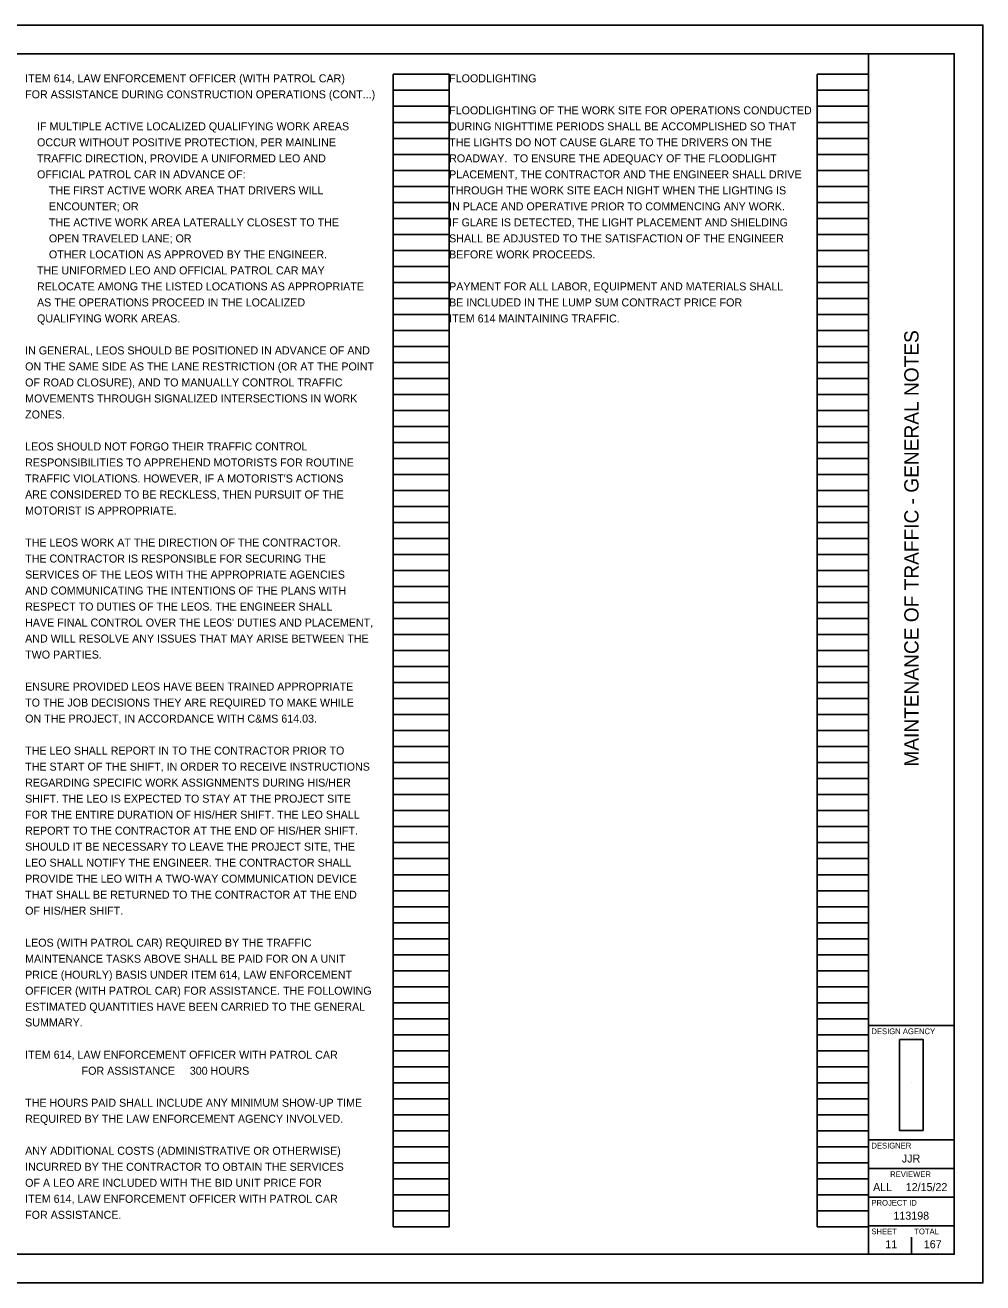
# Model space of a CAD drawing. Extents: x 0 to 34, y 0 to 22.
# Drawn here: x 17.24 to 34, y 0 to 22 of the extents above; entities that cross this region are included whole.
import ezdxf

# ---------------------------------------------------------------- set-up
doc = ezdxf.new("R2010")
doc.units = 0
for name, color, linetype in [('SH_Border', 7, 'Continuous'), ('SH_Cut_Line', 7, 'Continuous'), ('SH_Data', 7, 'Continuous'), ('SH_Text', 7, 'Continuous')]:
    doc.layers.add(name, color=color, linetype=linetype)

msp = doc.modelspace()

# ---------------------------------------------------------------- linework, layer by layer
at = {"layer": 'SH_Border'}
for p, q in [((32, 0.5), (32, 21.5)), ((32, 4.5), (33.5, 4.5)), ((32, 2.5), (33.5, 2.5)), ((32, 2), (33.5, 2)), ((32, 1.5), (33.5, 1.5)), ((32, 1), (33.5, 1))]:
    msp.add_line(p, q, dxfattribs=at)
msp.add_lwpolyline([(1.5, 21.5), (33.5, 21.5), (33.5, 0.5), (1.5, 0.5)], close=True, dxfattribs=at)
at = {"layer": 'SH_Cut_Line'}
msp.add_lwpolyline([(0, 0), (34, 0), (34, 22), (0, 22)], close=True, dxfattribs=at)
at = {"layer": 'SH_Data'}
for p, q in [((23.68, 0.98), (23.68, 21.14)), ((23.68, 21.14), (24.66, 21.14)), ((24.66, 0.98), (24.66, 21.14)), ((31.1, 0.98), (31.1, 21.14)), ((31.1, 21.14), (32, 21.14)), ((32, 0.98), (32, 21.14)), ((23.68, 20.86), (24.66, 20.86)), ((31.1, 20.86), (32, 20.86)), ((23.68, 20.58), (24.66, 20.58)), ((31.1, 20.58), (32, 20.58)), ((23.68, 20.3), (24.66, 20.3)), ((31.1, 20.3), (32, 20.3)), ((23.68, 20.02), (24.66, 20.02)), ((31.1, 20.02), (32, 20.02)), ((23.68, 19.74), (24.66, 19.74)), ((31.1, 19.74), (32, 19.74)), ((23.68, 19.46), (24.66, 19.46)), ((31.1, 19.46), (32, 19.46)), ((23.68, 19.18), (24.66, 19.18)), ((31.1, 19.18), (32, 19.18)), ((23.68, 18.9), (24.66, 18.9)), ((31.1, 18.9), (32, 18.9)), ((23.68, 18.62), (24.66, 18.62)), ((31.1, 18.62), (32, 18.62)), ((23.68, 18.34), (24.66, 18.34)), ((31.1, 18.34), (32, 18.34)), ((23.68, 18.06), (24.66, 18.06)), ((31.1, 18.06), (32, 18.06)), ((23.68, 17.78), (24.66, 17.78)), ((31.1, 17.78), (32, 17.78)), ((23.68, 17.5), (24.66, 17.5)), ((31.1, 17.5), (32, 17.5)), ((23.68, 17.22), (24.66, 17.22)), ((31.1, 17.22), (32, 17.22)), ((23.68, 16.94), (24.66, 16.94)), ((31.1, 16.94), (32, 16.94)), ((23.68, 16.66), (24.66, 16.66)), ((31.1, 16.66), (32, 16.66)), ((23.68, 16.38), (24.66, 16.38)), ((31.1, 16.38), (32, 16.38)), ((23.68, 16.1), (24.66, 16.1)), ((31.1, 16.1), (32, 16.1)), ((23.68, 15.82), (24.66, 15.82)), ((31.1, 15.82), (32, 15.82)), ((23.68, 15.54), (24.66, 15.54)), ((31.1, 15.54), (32, 15.54)), ((23.68, 15.26), (24.66, 15.26)), ((31.1, 15.26), (32, 15.26)), ((23.68, 14.98), (24.66, 14.98)), ((31.1, 14.98), (32, 14.98)), ((23.68, 14.7), (24.66, 14.7)), ((31.1, 14.7), (32, 14.7)), ((23.68, 14.42), (24.66, 14.42)), ((31.1, 14.42), (32, 14.42)), ((23.68, 14.14), (24.66, 14.14)), ((31.1, 14.14), (32, 14.14)), ((23.68, 13.86), (24.66, 13.86)), ((31.1, 13.86), (32, 13.86)), ((23.68, 13.58), (24.66, 13.58)), ((31.1, 13.58), (32, 13.58)), ((23.68, 13.3), (24.66, 13.3)), ((31.1, 13.3), (32, 13.3)), ((23.68, 13.02), (24.66, 13.02)), ((31.1, 13.02), (32, 13.02)), ((23.68, 12.74), (24.66, 12.74)), ((31.1, 12.74), (32, 12.74)), ((23.68, 12.46), (24.66, 12.46)), ((31.1, 12.46), (32, 12.46)), ((23.68, 12.18), (24.66, 12.18)), ((31.1, 12.18), (32, 12.18)), ((23.68, 11.9), (24.66, 11.9)), ((31.1, 11.9), (32, 11.9)), ((23.68, 11.62), (24.66, 11.62)), ((31.1, 11.62), (32, 11.62)), ((23.68, 11.34), (24.66, 11.34)), ((31.1, 11.34), (32, 11.34)), ((23.68, 11.06), (24.66, 11.06)), ((31.1, 11.06), (32, 11.06)), ((23.68, 10.78), (24.66, 10.78)), ((31.1, 10.78), (32, 10.78)), ((23.68, 10.5), (24.66, 10.5)), ((31.1, 10.5), (32, 10.5)), ((23.68, 10.22), (24.66, 10.22)), ((31.1, 10.22), (32, 10.22)), ((23.68, 9.94), (24.66, 9.94)), ((31.1, 9.94), (32, 9.94)), ((23.68, 9.66), (24.66, 9.66)), ((31.1, 9.66), (32, 9.66)), ((23.68, 9.38), (24.66, 9.38)), ((31.1, 9.38), (32, 9.38)), ((23.68, 9.1), (24.66, 9.1)), ((31.1, 9.1), (32, 9.1)), ((23.68, 8.82), (24.66, 8.82)), ((31.1, 8.82), (32, 8.82)), ((23.68, 8.54), (24.66, 8.54)), ((31.1, 8.54), (32, 8.54)), ((23.68, 8.26), (24.66, 8.26)), ((31.1, 8.26), (32, 8.26)), ((23.68, 7.98), (24.66, 7.98)), ((31.1, 7.98), (32, 7.98)), ((23.68, 7.7), (24.66, 7.7)), ((31.1, 7.7), (32, 7.7)), ((23.68, 7.42), (24.66, 7.42)), ((31.1, 7.42), (32, 7.42)), ((23.68, 7.14), (24.66, 7.14)), ((31.1, 7.14), (32, 7.14)), ((23.68, 6.86), (24.66, 6.86)), ((31.1, 6.86), (32, 6.86)), ((23.68, 6.58), (24.66, 6.58)), ((31.1, 6.58), (32, 6.58)), ((23.68, 6.3), (24.66, 6.3)), ((31.1, 6.3), (32, 6.3)), ((23.68, 6.02), (24.66, 6.02)), ((31.1, 6.02), (32, 6.02)), ((23.68, 5.74), (24.66, 5.74)), ((31.1, 5.74), (32, 5.74)), ((23.68, 5.46), (24.66, 5.46)), ((31.1, 5.46), (32, 5.46)), ((23.68, 5.18), (24.66, 5.18)), ((31.1, 5.18), (32, 5.18)), ((23.68, 4.9), (24.66, 4.9)), ((31.1, 4.9), (32, 4.9)), ((23.68, 4.62), (24.66, 4.62)), ((31.1, 4.62), (32, 4.62)), ((23.68, 4.34), (24.66, 4.34)), ((31.1, 4.34), (32, 4.34)), ((23.68, 4.06), (24.66, 4.06)), ((31.1, 4.06), (32, 4.06)), ((23.68, 3.78), (24.66, 3.78)), ((31.1, 3.78), (32, 3.78)), ((23.68, 3.5), (24.66, 3.5)), ((31.1, 3.5), (32, 3.5)), ((32.75, 3.5), (32.75, 3.5)), ((23.68, 3.22), (24.66, 3.22)), ((31.1, 3.22), (32, 3.22)), ((23.68, 2.94), (24.66, 2.94)), ((31.1, 2.94), (32, 2.94)), ((23.68, 2.66), (24.66, 2.66)), ((31.1, 2.66), (32, 2.66)), ((23.68, 2.38), (24.66, 2.38)), ((31.1, 2.38), (32, 2.38)), ((23.68, 2.1), (24.66, 2.1)), ((31.1, 2.1), (32, 2.1)), ((23.68, 1.82), (24.66, 1.82)), ((31.1, 1.82), (32, 1.82)), ((23.68, 1.54), (24.66, 1.54)), ((31.1, 1.54), (32, 1.54)), ((23.68, 1.26), (24.66, 1.26)), ((31.1, 1.26), (32, 1.26)), ((23.68, 0.98), (24.66, 0.98)), ((31.1, 0.98), (32, 0.98)), ((32.375, 0.675), (32.375, 0.675)), ((32.75, 0.5), (32.75, 0.8))]:
    msp.add_line(p, q, dxfattribs=at)
at = {"layer": 'SH_Text'}
msp.add_lwpolyline([(32.956, 2.664), (32.956, 4.254), (32.544, 4.254), (32.544, 2.664)], close=True, dxfattribs=at)

# ---------------------------------------------------------------- texts
at = {"layer": 'SH_Data'}
msp.add_text('MAINTENANCE OF TRAFFIC - GENERAL NOTES', height=0.25, rotation=90, dxfattribs=at).set_placement((32.875, 9.03))
for s, height, p in [('DESIGN AGENCY', 0.1, (32.05, 4.35)), ('DESIGNER', 0.1, (32.05, 2.35)), ('JJR', 0.14, (32.583, 2.105)), ('REVIEWER', 0.1, (32.378, 1.85)), ('ALL', 0.14, (32.079, 1.605)), ('12/15/22', 0.14, (32.65, 1.605)), ('PROJECT ID', 0.1, (32.05, 1.35)), ('113198', 0.14, (32.435, 1.105)), ('SHEET', 0.1, (32.05, 0.85)), ('TOTAL', 0.1, (32.8, 0.85)), ('11', 0.14, (32.292, 0.605)), ('167', 0.14, (32.966, 0.605))]:
    msp.add_text(s, height=height, dxfattribs=at).set_placement(p)
at = {"layer": 'SH_Text'}
for s, p in [('ITEM 614, LAW ENFORCEMENT OFFICER (WITH PATROL CAR)', (17.24, 21)), ('FLOODLIGHTING', (24.66, 21)), ('FOR ASSISTANCE DURING CONSTRUCTION OPERATIONS (CONT...)', (17.24, 20.72)), ('FLOODLIGHTING OF THE WORK SITE FOR OPERATIONS CONDUCTED', (24.66, 20.44)), ('    IF MULTIPLE ACTIVE LOCALIZED QUALIFYING WORK AREAS', (17.24, 20.16)), ('DURING NIGHTTIME PERIODS SHALL BE ACCOMPLISHED SO THAT', (24.66, 20.16)), ('    OCCUR WITHOUT POSITIVE PROTECTION, PER MAINLINE', (17.24, 19.88)), ('THE LIGHTS DO NOT CAUSE GLARE TO THE DRIVERS ON THE', (24.66, 19.88)), ('    TRAFFIC DIRECTION, PROVIDE A UNIFORMED LEO AND', (17.24, 19.6)), ('ROADWAY.  TO ENSURE THE ADEQUACY OF THE FLOODLIGHT', (24.66, 19.6)), ('    OFFICIAL PATROL CAR IN ADVANCE OF:', (17.24, 19.32)), ('PLACEMENT, THE CONTRACTOR AND THE ENGINEER SHALL DRIVE', (24.66, 19.32)), ('        THE FIRST ACTIVE WORK AREA THAT DRIVERS WILL', (17.24, 19.04)), ('THROUGH THE WORK SITE EACH NIGHT WHEN THE LIGHTING IS', (24.66, 19.04)), ('        ENCOUNTER; OR', (17.24, 18.76)), ('IN PLACE AND OPERATIVE PRIOR TO COMMENCING ANY WORK.', (24.66, 18.76)), ('        THE ACTIVE WORK AREA LATERALLY CLOSEST TO THE', (17.24, 18.48)), ('IF GLARE IS DETECTED, THE LIGHT PLACEMENT AND SHIELDING', (24.66, 18.48)), ('        OPEN TRAVELED LANE; OR', (17.24, 18.2)), ('SHALL BE ADJUSTED TO THE SATISFACTION OF THE ENGINEER', (24.66, 18.2)), ('        OTHER LOCATION AS APPROVED BY THE ENGINEER.', (17.24, 17.92)), ('BEFORE WORK PROCEEDS.', (24.66, 17.92)), ('    THE UNIFORMED LEO AND OFFICIAL PATROL CAR MAY', (17.24, 17.64)), ('    RELOCATE AMONG THE LISTED LOCATIONS AS APPROPRIATE', (17.24, 17.36)), ('PAYMENT FOR ALL LABOR, EQUIPMENT AND MATERIALS SHALL', (24.66, 17.36)), ('    AS THE OPERATIONS PROCEED IN THE LOCALIZED', (17.24, 17.08)), ('BE INCLUDED IN THE LUMP SUM CONTRACT PRICE FOR', (24.66, 17.08)), ('    QUALIFYING WORK AREAS.', (17.24, 16.8)), ('ITEM 614 MAINTAINING TRAFFIC.', (24.66, 16.8)), ('IN GENERAL, LEOS SHOULD BE POSITIONED IN ADVANCE OF AND', (17.24, 16.24)), ('ON THE SAME SIDE AS THE LANE RESTRICTION (OR AT THE POINT', (17.24, 15.96)), ('OF ROAD CLOSURE), AND TO MANUALLY CONTROL TRAFFIC', (17.24, 15.68)), ('MOVEMENTS THROUGH SIGNALIZED INTERSECTIONS IN WORK', (17.24, 15.4)), ('ZONES.', (17.24, 15.12)), ('LEOS SHOULD NOT FORGO THEIR TRAFFIC CONTROL', (17.24, 14.56)), ('RESPONSIBILITIES TO APPREHEND MOTORISTS FOR ROUTINE', (17.24, 14.28)), ("TRAFFIC VIOLATIONS. HOWEVER, IF A MOTORIST'S ACTIONS", (17.24, 14)), ('ARE CONSIDERED TO BE RECKLESS, THEN PURSUIT OF THE', (17.24, 13.72)), ('MOTORIST IS APPROPRIATE.', (17.24, 13.44)), ('THE LEOS WORK AT THE DIRECTION OF THE CONTRACTOR.', (17.24, 12.88)), ('THE CONTRACTOR IS RESPONSIBLE FOR SECURING THE', (17.24, 12.6)), ('SERVICES OF THE LEOS WITH THE APPROPRIATE AGENCIES', (17.24, 12.32)), ('AND COMMUNICATING THE INTENTIONS OF THE PLANS WITH', (17.24, 12.04)), ('RESPECT TO DUTIES OF THE LEOS. THE ENGINEER SHALL', (17.24, 11.76)), ("HAVE FINAL CONTROL OVER THE LEOS' DUTIES AND PLACEMENT,", (17.24, 11.48)), ('AND WILL RESOLVE ANY ISSUES THAT MAY ARISE BETWEEN THE', (17.24, 11.2)), ('TWO PARTIES.', (17.24, 10.92)), ('ENSURE PROVIDED LEOS HAVE BEEN TRAINED APPROPRIATE', (17.24, 10.36)), ('TO THE JOB DECISIONS THEY ARE REQUIRED TO MAKE WHILE', (17.24, 10.08)), ('ON THE PROJECT, IN ACCORDANCE WITH C&MS 614.03.', (17.24, 9.8)), ('THE LEO SHALL REPORT IN TO THE CONTRACTOR PRIOR TO', (17.24, 9.24)), ('THE START OF THE SHIFT, IN ORDER TO RECEIVE INSTRUCTIONS', (17.24, 8.96)), ('REGARDING SPECIFIC WORK ASSIGNMENTS DURING HIS/HER', (17.24, 8.68)), ('SHIFT. THE LEO IS EXPECTED TO STAY AT THE PROJECT SITE', (17.24, 8.4)), ('FOR THE ENTIRE DURATION OF HIS/HER SHIFT. THE LEO SHALL', (17.24, 8.12)), ('REPORT TO THE CONTRACTOR AT THE END OF HIS/HER SHIFT.', (17.24, 7.84)), ('SHOULD IT BE NECESSARY TO LEAVE THE PROJECT SITE, THE', (17.24, 7.56)), ('LEO SHALL NOTIFY THE ENGINEER. THE CONTRACTOR SHALL', (17.24, 7.28)), ('PROVIDE THE LEO WITH A TWO-WAY COMMUNICATION DEVICE', (17.24, 7)), ('THAT SHALL BE RETURNED TO THE CONTRACTOR AT THE END', (17.24, 6.72)), ('OF HIS/HER SHIFT.', (17.24, 6.44)), ('LEOS (WITH PATROL CAR) REQUIRED BY THE TRAFFIC', (17.24, 5.88)), ('MAINTENANCE TASKS ABOVE SHALL BE PAID FOR ON A UNIT', (17.24, 5.6)), ('PRICE (HOURLY) BASIS UNDER ITEM 614, LAW ENFORCEMENT', (17.24, 5.32)), ('OFFICER (WITH PATROL CAR) FOR ASSISTANCE. THE FOLLOWING', (17.24, 5.04)), ('ESTIMATED QUANTITIES HAVE BEEN CARRIED TO THE GENERAL', (17.24, 4.76)), ('SUMMARY.', (17.24, 4.485)), ('ITEM 614, LAW ENFORCEMENT OFFICER WITH PATROL CAR', (17.24, 3.92)), ('                   FOR ASSISTANCE     300 HOURS', (17.24, 3.64)), ('THE HOURS PAID SHALL INCLUDE ANY MINIMUM SHOW-UP TIME', (17.24, 3.08)), ('REQUIRED BY THE LAW ENFORCEMENT AGENCY INVOLVED.', (17.24, 2.8)), ('ANY ADDITIONAL COSTS (ADMINISTRATIVE OR OTHERWISE)', (17.24, 2.24)), ('INCURRED BY THE CONTRACTOR TO OBTAIN THE SERVICES', (17.24, 1.96)), ('OF A LEO ARE INCLUDED WITH THE BID UNIT PRICE FOR', (17.24, 1.68)), ('ITEM 614, LAW ENFORCEMENT OFFICER WITH PATROL CAR', (17.24, 1.4)), ('FOR ASSISTANCE.', (17.24, 1.12))]:
    msp.add_text(s, height=0.14, dxfattribs=at).set_placement(p)

doc.saveas('drawing.dxf')
